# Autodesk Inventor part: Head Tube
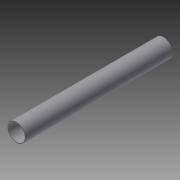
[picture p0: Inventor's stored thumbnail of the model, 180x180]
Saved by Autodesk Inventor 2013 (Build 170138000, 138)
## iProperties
Shininess: 64.0
Length Units: 11272
Angle Units: 11279
Time Units: 11290
Mass Units: 11286
Length Display Precision: 3
Angle Display Precision: 2
Compacted: True
Part Number: Head Tube
Document SubType Name: Modeling
Created: 2002-09
Designer: Autodesk, Inc.
Mass: 25.0785 g
Surface Area: 397.116 cm^2
Volume: 25.0785 cm^3
Density: 1 g/cm^3
Material: Generic
Density: 0.0
Volumn: 0.0
Area: 0.0
PropertySet Name: Model Information
Control State: 0
Master: False
Checked Out: False
Author: Autodesk, Inc.
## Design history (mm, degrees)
sketch "Sketch1"
  geometry: C1 r 14.287 at (0, 0); 1 further point
  constraints: 1 centre point, 1 coincident
  dimensions: "d0" = 28.575 diameter of C1 (= OD)
extrude "Extrusion1" new body sketch "Sketch1" distance "d1" = 230.2002; taper "d2" = 0 deg
shell "Shell1" dims "d3" = 1.27
body "Solid1"
other parameters: "OD" = 28.575 [user parameter; used in 1 equation term]
